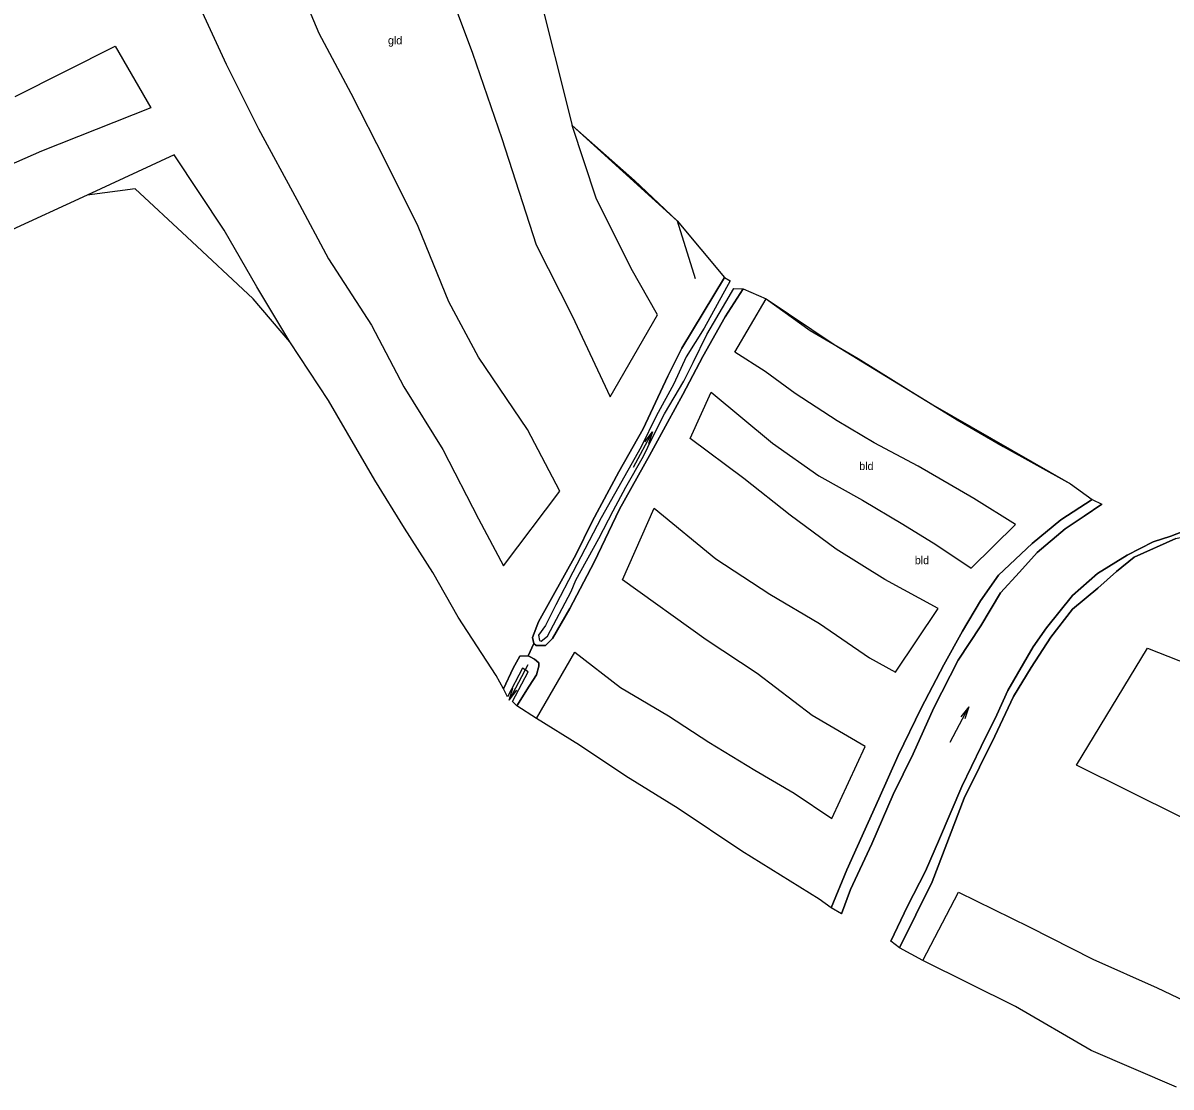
# Model space of a CAD drawing. Extents: x 154825 to 158680, y 370717 to 378075.
# Drawn here: x 157336.6 to 157480, y 372512.4 to 372645.4 of the extents above; entities that cross this region are included whole.
import ezdxf

# ---------------------------------------------------------------- set-up
doc = ezdxf.new("R2010")
doc.units = 0
for name, color, linetype in [('bouwland_akkerland(vs)', 7, 'Continuous'), ('breuklijn', 7, 'Continuous'), ('cultuurscheiding', 7, 'Continuous'), ('grasland_productiegrasl(vs)', 7, 'Continuous'), ('hoogteverschillijn', 7, 'Continuous'), ('insteek sloot', 7, 'Continuous'), ('Sloot bodem', 7, 'Continuous'), ('stroomrichting  watergangen', 7, 'Continuous'), ('vlak_akkerland', 7, 'Continuous'), ('vlak_Grasland', 7, 'Continuous'), ('vlak_Grazige_vegetatie', 7, 'Continuous')]:
    doc.layers.add(name, color=color, linetype=linetype)

msp = doc.modelspace()

# ---------------------------------------------------------------- linework, layer by layer
at = {"layer": 'breuklijn'}
msp.add_lwpolyline([(157517.77, 372526.67), (157501.49, 372535.34), (157491.32, 372541.11), (157481.22, 372546.14), (157468.2, 372552.58), (157477.08, 372567.22), (157492.53, 372561.13)], dxfattribs=at)
at = {"layer": 'cultuurscheiding'}
msp.add_lwpolyline([(157399.68, 372566.23), (157400.39, 372567.78)], dxfattribs=at)
at = {"layer": 'hoogteverschillijn'}
for points in [[(157358.47, 372647.79), (157361.96, 372640.18), (157366.01, 372632.1), (157370.8, 372623.29), (157374.74, 372615.85), (157380.14, 372607.59), (157384.15, 372599.86), (157389.04, 372592.02), (157393.49, 372583.38), (157396.61, 372577.51), (157403.66, 372586.83), (157399.63, 372594.53), (157393.48, 372603.57), (157389.78, 372610.48), (157385.95, 372619.89), (157381.87, 372628.1), (157377.58, 372636.55), (157373.6, 372644.05), (157369.45, 372653.86)], [(157389.16, 372651.22), (157392.74, 372641.59), (157396.39, 372630.9), (157400.69, 372617.61), (157405.19, 372608.73), (157409.93, 372598.64), (157415.86, 372608.85), (157412.58, 372614.64), (157408.21, 372623.47), (157405.18, 372632.54), (157412.98, 372625.65), (157418.33, 372620.62), (157420.56, 372613.39)], [(157335.59, 372636.14), (157348.08, 372642.47), (157352.55, 372634.73), (157338.9, 372629.34), (157328.08, 372624.58)], [(157395.69, 372563.77), (157390.96, 372571.07), (157387.8, 372576.66), (157384.26, 372582.21), (157380.53, 372588.19), (157374.76, 372598.15), (157369.94, 372605.49), (157365.79, 372612.37), (157361.7, 372619.47), (157355.48, 372628.87), (157344.58, 372623.83), (157334.65, 372619.26)], [(157350.59, 372624.62), (157357.05, 372618.6), (157365.35, 372610.88)], [(157436.05, 372535.84), (157426.39, 372541.82), (157418.44, 372547.16), (157411.91, 372551.19), (157406.13, 372555.09), (157400.76, 372558.42), (157405.54, 372566.72), (157411.22, 372562.3), (157417.25, 372558.73), (157422.27, 372555.46), (157428.03, 372551.95), (157432.93, 372549.08), (157437.66, 372545.92), (157441.82, 372554.93), (157435.19, 372558.81), (157428.3, 372564.03), (157421.93, 372568.25), (157411.48, 372575.73), (157415.45, 372584.71), (157423.16, 372578.37), (157429.9, 372573.96), (157436.1, 372570.28), (157442.34, 372566.01), (157445.59, 372564.19), (157450.92, 372572.15), (157444.25, 372575.77), (157438.18, 372579.59), (157432.44, 372583.83), (157426.63, 372588.43), (157419.94, 372593.43), (157422.57, 372599.21), (157430.23, 372592.84), (157436.01, 372588.76), (157441.48, 372585.7), (157446.52, 372582.72), (157450.65, 372580.16), (157455.07, 372577.21), (157460.6, 372582.68), (157455.39, 372585.93), (157448.42, 372589.97), (157442.92, 372592.89), (157438.3, 372595.61), (157433.05, 372599.03), (157429.32, 372601.77), (157425.54, 372604.19), (157429.43, 372610.85), (157434.92, 372606.91), (157440.94, 372603.42), (157447.23, 372599.49), (157453.31, 372595.75), (157459.04, 372592.41), (157467.48, 372587.74)], [(157480.71, 372512.35), (157470.03, 372516.9), (157460.58, 372522.42), (157449.03, 372528.18), (157453.48, 372536.69), (157462.29, 372532.36), (157470.24, 372528.32), (157478.28, 372524.74), (157486.86, 372520.67)]]:
    msp.add_lwpolyline(points, dxfattribs=at)
at = {"layer": 'insteek sloot'}
for points in [[(157426.55, 372612.12), (157424.33, 372608.61), (157421.51, 372603.67), (157419.02, 372598.91), (157417.1, 372595.42), (157414.84, 372591.27), (157411.1, 372584.6), (157407.96, 372577.94), (157404.92, 372572.16), (157402.76, 372568.42), (157401.86, 372567.52), (157400.7, 372567.53), (157400.39, 372567.78), (157400.26, 372568.55), (157401, 372570.48), (157405.65, 372578.86), (157407.71, 372583.02), (157411.03, 372589.24), (157414.07, 372594.63), (157417.15, 372601.19), (157418.89, 372604.71), (157424.22, 372613.53)], [(157470.16, 372585.79), (157466.25, 372583.25), (157462.69, 372580.27), (157458.47, 372576.33), (157456.24, 372573.12), (157453.97, 372569.33), (157451.63, 372565.13), (157448.82, 372559.69), (157445.93, 372553.77), (157443.52, 372548.39), (157439.51, 372539.52), (157437.58, 372534.74)], [(157446.11, 372529.76), (157450.17, 372538), (157454.19, 372548.46), (157458.01, 372556.2), (157460.34, 372561.15), (157462.54, 372564.77), (157465, 372568.6), (157467.73, 372572.1), (157470.86, 372574.69), (157473.23, 372576.8), (157475.44, 372578.59), (157480.61, 372580.91), (157487.57, 372582.55), (157487.56, 372582.61)], [(157398.28, 372559.98), (157399.82, 372562.47), (157400.76, 372563.89), (157401.05, 372564.96), (157401.04, 372565.36), (157400.49, 372565.82), (157399.94, 372566.12), (157399.68, 372566.23), (157398.65, 372566.2), (157397.82, 372564.7), (157396.62, 372562.13)]]:
    msp.add_lwpolyline(points, dxfattribs=at)
at = {"layer": 'Sloot bodem'}
for points in [[(157424.92, 372613.1), (157421.71, 372607.22), (157419.44, 372603.62), (157417.92, 372600.24), (157415.68, 372596.2), (157413.8, 372592.35), (157408.82, 372583.49), (157405.3, 372576.72), (157403.16, 372572.63), (157401.85, 372570.02), (157401.01, 372568.84), (157401.12, 372568.15), (157401.31, 372568.06), (157402.1, 372568.7), (157405.06, 372574.27), (157405.65, 372575.7), (157408.51, 372580.93), (157410.3, 372584.39), (157411.91, 372587.34), (157414.1, 372591.22), (157415.2, 372593.47), (157416.75, 372596.51), (157419.14, 372600.56), (157420.33, 372602.9), (157422.02, 372606.4), (157424.39, 372610.45), (157425.4, 372612.16)], [(157438.85, 372534.01), (157439.99, 372537.05), (157442.66, 372542.75), (157445.29, 372548.91), (157447.79, 372553.98), (157450.4, 372559.76), (157453.44, 372565.7), (157456.26, 372570.01), (157458.7, 372574.12), (157461.08, 372576.7), (157463.3, 372579.18), (157466.79, 372582.14), (157469.17, 372583.72), (157471.36, 372585.21)], [(157487.18, 372584.01), (157480, 372581.2), (157477.79, 372580.49), (157474.53, 372578.83), (157470.83, 372576.54), (157467.73, 372573.77), (157464.45, 372569.74), (157462.82, 372567.36), (157459.63, 372561.93), (157458.28, 372558.89), (157456.29, 372554.93), (157453.9, 372549.92), (157451.1, 372543.37), (157449.36, 372539.33), (157447.08, 372534.96), (157445, 372530.59)], [(157397.75, 372560.54), (157399.71, 372564.23), (157398.99, 372564.7), (157397.12, 372561.14)]]:
    msp.add_lwpolyline(points, dxfattribs=at)
at = {"layer": 'stroomrichting  watergangen'}
for p, q in [((157412.87, 372589.84), (157415.23, 372594.24)), ((157415.21, 372594.23), (157414.23, 372592.99)), ((157415.23, 372594.24), (157414.73, 372592.74)), ((157399.66, 372565.11), (157397.31, 372560.7)), ((157397.31, 372560.7), (157397.8, 372562.2)), ((157397.33, 372560.71), (157398.3, 372561.95)), ((157452.41, 372555.47), (157454.77, 372559.87)), ((157454.75, 372559.87), (157453.77, 372558.62)), ((157454.77, 372559.87), (157454.28, 372558.37))]:
    msp.add_line(p, q, dxfattribs=at)
at = {"layer": 'vlak_akkerland'}
msp.add_lwpolyline([(157453.97, 372569.33), (157451.63, 372565.13), (157448.82, 372559.69), (157445.93, 372553.77), (157443.52, 372548.39), (157439.51, 372539.52), (157437.58, 372534.74), (157436.05, 372535.84), (157426.39, 372541.82), (157418.44, 372547.16), (157411.91, 372551.19), (157406.13, 372555.09), (157400.76, 372558.42), (157398.28, 372559.98), (157399.82, 372562.47), (157400.76, 372563.89), (157401.05, 372564.96), (157401.04, 372565.36), (157400.49, 372565.82), (157399.94, 372566.12), (157399.68, 372566.23), (157400.39, 372567.78), (157400.7, 372567.53), (157401.86, 372567.52), (157402.76, 372568.42), (157404.92, 372572.16), (157407.96, 372577.94), (157411.1, 372584.6), (157414.84, 372591.27), (157417.1, 372595.42), (157419.02, 372598.91), (157421.51, 372603.67), (157424.33, 372608.61), (157426.55, 372612.12), (157429.43, 372610.85), (157437.93, 372605.16), (157450.27, 372597.62), (157467.48, 372587.74), (157470.16, 372585.79), (157466.25, 372583.25), (157462.69, 372580.27), (157458.47, 372576.33), (157456.24, 372573.12)], close=True, dxfattribs=at)
msp.add_lwpolyline([(157480.71, 372512.35), (157470.03, 372516.9), (157460.58, 372522.42), (157449.03, 372528.18), (157446.11, 372529.76), (157450.17, 372538), (157454.19, 372548.46), (157458.01, 372556.2), (157460.34, 372561.15), (157462.54, 372564.77), (157465, 372568.6), (157467.73, 372572.1), (157470.86, 372574.69), (157473.23, 372576.8), (157475.44, 372578.59), (157480.61, 372580.91)], dxfattribs=at)
at = {"layer": 'vlak_Grasland'}
msp.add_lwpolyline([(157400.83, 372649.98), (157405.18, 372632.54), (157418.33, 372620.62), (157424.22, 372613.53), (157418.89, 372604.71), (157417.15, 372601.19), (157414.07, 372594.63), (157411.03, 372589.24), (157407.71, 372583.02), (157405.65, 372578.86), (157401, 372570.48), (157400.26, 372568.55), (157400.39, 372567.78), (157399.68, 372566.23), (157398.65, 372566.2), (157397.82, 372564.7), (157396.62, 372562.13), (157395.69, 372563.77), (157390.96, 372571.07), (157387.8, 372576.66), (157384.26, 372582.21), (157380.53, 372588.19), (157374.76, 372598.15), (157369.94, 372605.49), (157365.35, 372610.88), (157357.05, 372618.6), (157350.59, 372624.62), (157344.58, 372623.83), (157334.65, 372619.26)], dxfattribs=at)
at = {"layer": 'vlak_Grazige_vegetatie'}
for points in [[(157401.12, 372568.15), (157401.31, 372568.06), (157402.1, 372568.7), (157405.06, 372574.27), (157405.65, 372575.7), (157408.51, 372580.93), (157410.3, 372584.39), (157411.91, 372587.34), (157414.1, 372591.22), (157415.2, 372593.47), (157416.75, 372596.51), (157419.14, 372600.56), (157420.33, 372602.9), (157422.02, 372606.4), (157424.39, 372610.45), (157425.4, 372612.16), (157426.55, 372612.12), (157424.33, 372608.61), (157421.51, 372603.67), (157419.02, 372598.91), (157417.1, 372595.42), (157414.84, 372591.27), (157411.1, 372584.6), (157407.96, 372577.94), (157404.92, 372572.16), (157402.76, 372568.42), (157401.86, 372567.52), (157400.7, 372567.53), (157400.39, 372567.78), (157400.26, 372568.55), (157401, 372570.48), (157405.65, 372578.86), (157407.71, 372583.02), (157411.03, 372589.24), (157414.07, 372594.63), (157417.15, 372601.19), (157418.89, 372604.71), (157424.22, 372613.53), (157424.92, 372613.1), (157421.71, 372607.22), (157419.44, 372603.62), (157417.92, 372600.24), (157415.68, 372596.2), (157413.8, 372592.35), (157408.82, 372583.49), (157405.3, 372576.72), (157403.16, 372572.63), (157401.85, 372570.02), (157401.01, 372568.84)], [(157439.99, 372537.05), (157438.85, 372534.01), (157437.58, 372534.74), (157439.51, 372539.52), (157443.52, 372548.39), (157445.93, 372553.77), (157448.82, 372559.69), (157451.63, 372565.13), (157453.97, 372569.33), (157456.24, 372573.12), (157458.47, 372576.33), (157462.69, 372580.27), (157466.25, 372583.25), (157470.16, 372585.79), (157471.36, 372585.21), (157469.17, 372583.72), (157466.79, 372582.14), (157463.3, 372579.18), (157461.08, 372576.7), (157458.7, 372574.12), (157456.26, 372570.01), (157453.44, 372565.7), (157450.4, 372559.76), (157447.79, 372553.98), (157445.29, 372548.91), (157442.66, 372542.75)], [(157401.05, 372564.96), (157400.76, 372563.89), (157399.82, 372562.47), (157398.28, 372559.98), (157397.75, 372560.54), (157399.71, 372564.23), (157398.99, 372564.7), (157397.12, 372561.14), (157396.62, 372562.13), (157397.82, 372564.7), (157398.65, 372566.2), (157399.68, 372566.23), (157399.94, 372566.12), (157400.49, 372565.82), (157401.04, 372565.36)]]:
    msp.add_lwpolyline(points, close=True, dxfattribs=at)
msp.add_lwpolyline([(157480.61, 372580.91), (157475.44, 372578.59), (157473.23, 372576.8), (157470.86, 372574.69), (157467.73, 372572.1), (157465, 372568.6), (157462.54, 372564.77), (157460.34, 372561.15), (157458.01, 372556.2), (157454.19, 372548.46), (157450.17, 372538), (157446.11, 372529.76), (157445, 372530.59), (157447.08, 372534.96), (157449.36, 372539.33), (157451.1, 372543.37), (157453.9, 372549.92), (157456.29, 372554.93), (157458.28, 372558.89), (157459.63, 372561.93), (157462.82, 372567.36), (157464.45, 372569.74), (157467.73, 372573.77), (157470.83, 372576.54), (157474.53, 372578.83), (157477.79, 372580.49), (157480, 372581.2), (157487.18, 372584.01)], dxfattribs=at)

# ---------------------------------------------------------------- texts
at = {"layer": 'bouwland_akkerland(vs)'}
for p in [(157441.07, 372589.47), (157448.01, 372577.7)]:
    msp.add_text('bld', height=1, dxfattribs=at).set_placement(p)
at = {"layer": 'grasland_productiegrasl(vs)'}
msp.add_text('gld', height=1, dxfattribs=at).set_placement((157382.18, 372642.68))

doc.saveas('drawing.dxf')
